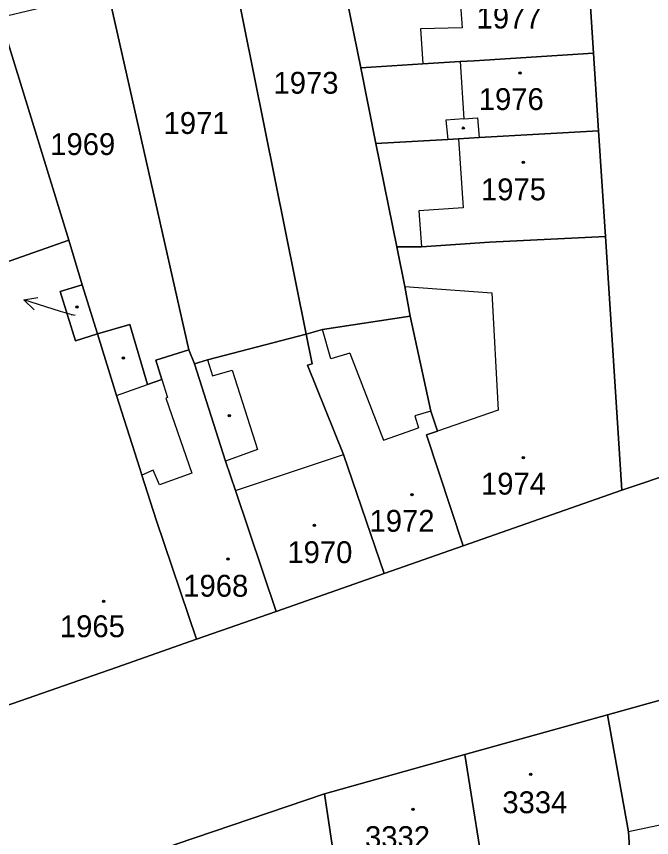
# Model space of a CAD drawing. Extents: x -596233 to -595156, y -1161235 to -1159375.
# Drawn here: x -595667.2 to -595617.7, y -1161083.2 to -1161019.3 of the extents above; entities that cross this region are included whole.
import ezdxf

# ---------------------------------------------------------------- set-up
doc = ezdxf.new("R2010")
doc.units = 0
for name, color, linetype in [('KN_CAR_KR', 7, 'Continuous'), ('KN_KULTURY', 7, 'Continuous'), ('KN_PARC_CIS_POM', 7, 'Continuous'), ('KN_PARC_CIS_POZ', 7, 'Continuous'), ('KN_PARC_CIS_STAV', 7, 'Continuous'), ('KN_PARC_PLOCHA', 7, 'Continuous'), ('PARC_C_SIPKA', 7, 'Continuous'), ('parcely_l', 7, 'Continuous')]:
    doc.layers.add(name, color=color, linetype=linetype)

msp = doc.modelspace()

# ---------------------------------------------------------------- linework, layer by layer
at = {"layer": 'KN_CAR_KR'}
for points in [[(-595632.78, -1161016), (-595632.49, -1161020.24)], [(-595632.49, -1161020.24), (-595635.72, -1161020.3)], [(-595635.72, -1161020.3), (-595635.55, -1161023.04)], [(-595632.63, -1161022.85), (-595632.35, -1161027.31)], [(-595632.35, -1161027.31), (-595633.74, -1161027.41)], [(-595632.35, -1161027.31), (-595631.28, -1161027.23)], [(-595631.28, -1161027.23), (-595631.15, -1161028.76)], [(-595633.74, -1161027.41), (-595633.6, -1161028.9)], [(-595632.76, -1161028.86), (-595632.4, -1161034.22)], [(-595632.4, -1161034.22), (-595635.84, -1161034.46)], [(-595635.84, -1161034.46), (-595635.65, -1161037.25)], [(-595636.93, -1161040.34), (-595630.16, -1161040.83)], [(-595630.16, -1161040.83), (-595629.68, -1161049.97)], [(-595642.7, -1161045.96), (-595643.34, -1161043.68)], [(-595641.22, -1161045.54), (-595642.7, -1161045.96)], [(-595641.22, -1161045.54), (-595638.59, -1161052.3)], [(-595652.28, -1161046.05), (-595651.91, -1161047.29)], [(-595651.91, -1161047.29), (-595650.38, -1161046.84)], [(-595650.38, -1161046.84), (-595648.39, -1161053.02)], [(-595655.84, -1161047.59), (-595655.41, -1161048.98)], [(-595659.38, -1161048.81), (-595656.97, -1161047.98)], [(-595655.41, -1161048.98), (-595655.54, -1161049.02)], [(-595655.54, -1161049.02), (-595653.51, -1161054.86)], [(-595634.91, -1161050.04), (-595636.15, -1161050.4)], [(-595629.68, -1161049.97), (-595634.4, -1161051.59)], [(-595636.15, -1161050.4), (-595635.87, -1161051.34)], [(-595638.59, -1161052.3), (-595635.87, -1161051.34)], [(-595648.39, -1161053.02), (-595650.88, -1161053.92)], [(-595650.11, -1161056.21), (-595641.72, -1161053.4)], [(-595656.53, -1161054.63), (-595657.39, -1161055.02)], [(-595656.02, -1161055.76), (-595656.53, -1161054.63)], [(-595653.51, -1161054.86), (-595656.02, -1161055.76)], [(-595615.99, -1161082), (-595619.53, -1161082.77)]]:
    msp.add_lwpolyline(points, dxfattribs=at)
at = {"layer": 'KN_KULTURY'}
for centre, radius in [((-595627.99, -1161023.75), 0.09), ((-595627.99, -1161023.75), 0.0398), ((-595632.4, -1161028.03), 0.09), ((-595632.4, -1161028.03), 0.0398), ((-595627.73, -1161030.69), 0.09), ((-595627.73, -1161030.69), 0.0398), ((-595662.45, -1161041.95), 0.09), ((-595662.45, -1161041.95), 0.0398), ((-595658.83, -1161045.91), 0.09), ((-595658.83, -1161045.91), 0.0398), ((-595650.6, -1161050.4), 0.09), ((-595650.6, -1161050.4), 0.0398), ((-595627.73, -1161053.65), 0.09), ((-595627.73, -1161053.65), 0.0398), ((-595636.38, -1161056.53), 0.09), ((-595636.38, -1161056.53), 0.0398), ((-595643.97, -1161058.93), 0.09), ((-595643.97, -1161058.93), 0.0398), ((-595650.7, -1161061.53), 0.09), ((-595650.7, -1161061.53), 0.0398), ((-595660.37, -1161064.84), 0.09), ((-595660.37, -1161064.84), 0.0398), ((-595627.14, -1161078.28), 0.09), ((-595627.14, -1161078.28), 0.0398), ((-595636.31, -1161081.01), 0.09), ((-595636.31, -1161081.01), 0.0398)]:
    msp.add_circle(centre, radius, dxfattribs=at)
at = {"layer": 'KN_PARC_PLOCHA'}
for points in [[(-595642.85, -1161010.99), (-595641.73, -1161016.57), (-595640.37, -1161023.34), (-595639.19, -1161029.22), (-595637.57, -1161037.26), (-595636.93, -1161040.34), (-595636.52, -1161042.66), (-595643.34, -1161043.68), (-595644.61, -1161044.04), (-595651.1, -1161011.83), (-595643.22, -1161009.14)], [(-595644.61, -1161044.04), (-595652.28, -1161046.05), (-595653.29, -1161046.35), (-595653.75, -1161045.27), (-595660.01, -1161017.46), (-595652.54, -1161012.74), (-595651.1, -1161011.83)], [(-595622.26, -1161022.21), (-595631.54, -1161022.79), (-595632.63, -1161022.85), (-595635.55, -1161023.04), (-595640.37, -1161023.34), (-595641.73, -1161016.57), (-595637.17, -1161016.28), (-595635.09, -1161016.14), (-595632.78, -1161016), (-595632.06, -1161015.95), (-595622.71, -1161015.36)], [(-595653.75, -1161045.27), (-595656.32, -1161046.07), (-595655.84, -1161047.59), (-595656.97, -1161047.98), (-595658.34, -1161043.3), (-595660.85, -1161044.03), (-595662.03, -1161040.21), (-595663.09, -1161036.75), (-595668.42, -1161019.4), (-595667.82, -1161019.28), (-595661.7, -1161017.8), (-595660.01, -1161017.46)], [(-595663.09, -1161036.75), (-595679.52, -1161042.53), (-595684.35, -1161029.96), (-595684.76, -1161028.79), (-595686.21, -1161024.68), (-595685.24, -1161024.28), (-595679.66, -1161022.52), (-595676.85, -1161021.56), (-595675.3, -1161021.09), (-595668.42, -1161019.4)], [(-595621.87, -1161028.23), (-595631.15, -1161028.76), (-595632.76, -1161028.86), (-595633.6, -1161028.9), (-595639.19, -1161029.22), (-595640.37, -1161023.34), (-595635.55, -1161023.04), (-595632.63, -1161022.85), (-595631.54, -1161022.79), (-595622.26, -1161022.21)], [(-595621.33, -1161036.46), (-595630.36, -1161036.9), (-595635.65, -1161037.25), (-595637.57, -1161037.26), (-595639.19, -1161029.22), (-595633.6, -1161028.9), (-595632.76, -1161028.86), (-595631.15, -1161028.76), (-595621.87, -1161028.23)], [(-595662.03, -1161040.21), (-595663.75, -1161040.74), (-595662.57, -1161044.56), (-595660.85, -1161044.03), (-595659.38, -1161048.81), (-595657.56, -1161054.5), (-595657.39, -1161055.02), (-595656.28, -1161058.5), (-595653.15, -1161067.78), (-595659.4, -1161069.97), (-595668.03, -1161072.98), (-595671.17, -1161064.61), (-595671.4, -1161064), (-595673.91, -1161057.31), (-595675.45, -1161053.19), (-595676.47, -1161050.46), (-595679.52, -1161042.53), (-595663.09, -1161036.75)], [(-595620.07, -1161056.19), (-595632.4, -1161060.51), (-595635.26, -1161051.88), (-595634.4, -1161051.59), (-595634.91, -1161050.04), (-595636.52, -1161042.66), (-595636.93, -1161040.34), (-595637.57, -1161037.26), (-595635.65, -1161037.25), (-595630.36, -1161036.9), (-595621.33, -1161036.46)], [(-595660.85, -1161044.03), (-595662.57, -1161044.56), (-595663.75, -1161040.74), (-595662.03, -1161040.21)], [(-595632.4, -1161060.51), (-595638.56, -1161062.67), (-595641.72, -1161053.4), (-595644.5, -1161046.46), (-595644.14, -1161046.36), (-595644.61, -1161044.04), (-595643.34, -1161043.68), (-595636.52, -1161042.66), (-595634.91, -1161050.04), (-595634.4, -1161051.59), (-595635.26, -1161051.88)], [(-595653.75, -1161045.27), (-595653.29, -1161046.35), (-595650.88, -1161053.92), (-595650.11, -1161056.21), (-595646.96, -1161065.61), (-595653.15, -1161067.78), (-595656.28, -1161058.5), (-595657.39, -1161055.02), (-595657.56, -1161054.5), (-595659.38, -1161048.81), (-595660.85, -1161044.03), (-595658.34, -1161043.3), (-595656.97, -1161047.98), (-595655.84, -1161047.59), (-595656.32, -1161046.07)], [(-595638.56, -1161062.67), (-595646.96, -1161065.61), (-595650.11, -1161056.21), (-595650.88, -1161053.92), (-595653.29, -1161046.35), (-595652.28, -1161046.05), (-595644.61, -1161044.04), (-595644.14, -1161046.36), (-595644.5, -1161046.46), (-595641.72, -1161053.4)], [(-595607.09, -1161088.75), (-595609.57, -1161089.08), (-595613.96, -1161089.04), (-595612.93, -1161095.54), (-595614.07, -1161095.65), (-595613.85, -1161097.15), (-595611.29, -1161096.84), (-595610.21, -1161105.21), (-595615.88, -1161105.95), (-595616.55, -1161101.2), (-595616.89, -1161101.2), (-595617.01, -1161101.2), (-595618.37, -1161092.42), (-595618.17, -1161092.39), (-595618.81, -1161088.35), (-595619.43, -1161084.4), (-595619.53, -1161082.77), (-595621.16, -1161073.65), (-595610.09, -1161070.58), (-595607.88, -1161079.68), (-595607.57, -1161083.19), (-595607.4, -1161085.24)], [(-595618.81, -1161088.35), (-595623.67, -1161088.91), (-595621.72, -1161107.66), (-595627.25, -1161108.52), (-595628, -1161103.71), (-595628.6, -1161099.94), (-595630.54, -1161087.63), (-595632.26, -1161076.75), (-595621.16, -1161073.65), (-595619.53, -1161082.77), (-595619.43, -1161084.4)], [(-595627.25, -1161108.52), (-595631.54, -1161109.12), (-595632.8, -1161109.28), (-595632.28, -1161113.48), (-595637.94, -1161114.26), (-595638.17, -1161112.67), (-595638.53, -1161110.1), (-595638.63, -1161109.2), (-595640.62, -1161096.67), (-595641.33, -1161091.91), (-595641.61, -1161090.39), (-595643.19, -1161079.8), (-595632.26, -1161076.75), (-595630.54, -1161087.63), (-595628.6, -1161099.94), (-595628, -1161103.71)], [(-595638.17, -1161112.67), (-595643.45, -1161113.53), (-595649.52, -1161114.51), (-595650.42, -1161109.18), (-595654.73, -1161083.72), (-595643.19, -1161079.8), (-595641.61, -1161090.39), (-595641.33, -1161091.91), (-595640.62, -1161096.67), (-595638.63, -1161109.2), (-595638.53, -1161110.1)]]:
    msp.add_lwpolyline(points, close=True, dxfattribs=at)
for points in [[(-595606.83, -1161051.74), (-595620.07, -1161056.19), (-595621.33, -1161036.46), (-595621.87, -1161028.23), (-595622.26, -1161022.21), (-595622.71, -1161015.36)], [(-595735.63, -1161096.54), (-595722.22, -1161091.87), (-595715.29, -1161089.45), (-595708.59, -1161087.12), (-595695.01, -1161082.38), (-595688.66, -1161080.17), (-595681.37, -1161077.63), (-595674.79, -1161075.34), (-595674.36, -1161075.19), (-595673.59, -1161074.92), (-595668.03, -1161072.98), (-595659.4, -1161069.97), (-595653.15, -1161067.78), (-595646.96, -1161065.61), (-595638.56, -1161062.67), (-595632.4, -1161060.51), (-595620.07, -1161056.19), (-595606.83, -1161051.74)], [(-595610.09, -1161070.58), (-595621.16, -1161073.65), (-595632.26, -1161076.75), (-595643.19, -1161079.8), (-595654.73, -1161083.72), (-595665.41, -1161087.54), (-595676.29, -1161091.44), (-595688.25, -1161095.72), (-595700.38, -1161100.11), (-595712.11, -1161104.36), (-595718, -1161106.49), (-595723.82, -1161108.53), (-595729.91, -1161110.67), (-595735.77, -1161112.73)]]:
    msp.add_lwpolyline(points, dxfattribs=at)
at = {"layer": 'PARC_C_SIPKA'}
for points in [[(-595665.7784, -1161042.166), (-595666.5858, -1161041.3926), (-595665.4826, -1161041.2108)], [(-595662.65, -1161042.61), (-595663.72, -1161042.28), (-595666.5858, -1161041.3926)]]:
    msp.add_lwpolyline(points, dxfattribs=at)
at = {"layer": 'parcely_l'}
for points in [[(-595644.61, -1161044.04), (-595651.1, -1161011.83)], [(-595622.71, -1161015.36), (-595622.26, -1161022.21)], [(-595641.73, -1161016.57), (-595640.37, -1161023.34)], [(-595653.75, -1161045.27), (-595660.01, -1161017.46)], [(-595668.42, -1161019.4), (-595663.09, -1161036.75)], [(-595622.26, -1161022.21), (-595631.54, -1161022.79), (-595632.63, -1161022.85), (-595635.55, -1161023.04), (-595640.37, -1161023.34)], [(-595622.26, -1161022.21), (-595621.87, -1161028.23)], [(-595640.37, -1161023.34), (-595639.19, -1161029.22)], [(-595639.19, -1161029.22), (-595633.6, -1161028.9), (-595632.76, -1161028.86), (-595631.15, -1161028.76), (-595621.87, -1161028.23)], [(-595621.87, -1161028.23), (-595621.33, -1161036.46)], [(-595639.19, -1161029.22), (-595637.57, -1161037.26)], [(-595663.09, -1161036.75), (-595679.52, -1161042.53)], [(-595662.03, -1161040.21), (-595663.09, -1161036.75)], [(-595637.57, -1161037.26), (-595635.65, -1161037.25), (-595630.36, -1161036.9), (-595621.33, -1161036.46)], [(-595621.33, -1161036.46), (-595620.07, -1161056.19)], [(-595636.52, -1161042.66), (-595636.93, -1161040.34), (-595637.57, -1161037.26)], [(-595660.85, -1161044.03), (-595662.57, -1161044.56), (-595663.75, -1161040.74), (-595662.03, -1161040.21)], [(-595662.03, -1161040.21), (-595660.85, -1161044.03)], [(-595644.61, -1161044.04), (-595643.34, -1161043.68), (-595636.52, -1161042.66)], [(-595636.52, -1161042.66), (-595634.91, -1161050.04), (-595634.4, -1161051.59), (-595635.26, -1161051.88), (-595632.4, -1161060.51)], [(-595660.85, -1161044.03), (-595658.34, -1161043.3), (-595656.97, -1161047.98), (-595655.84, -1161047.59), (-595656.32, -1161046.07), (-595653.75, -1161045.27)], [(-595653.15, -1161067.78), (-595656.28, -1161058.5), (-595657.39, -1161055.02), (-595657.56, -1161054.5), (-595659.38, -1161048.81), (-595660.85, -1161044.03)], [(-595644.61, -1161044.04), (-595652.28, -1161046.05), (-595653.29, -1161046.35)], [(-595638.56, -1161062.67), (-595641.72, -1161053.4), (-595644.5, -1161046.46), (-595644.14, -1161046.36), (-595644.61, -1161044.04)], [(-595653.29, -1161046.35), (-595653.75, -1161045.27)], [(-595646.96, -1161065.61), (-595650.11, -1161056.21), (-595650.88, -1161053.92), (-595653.29, -1161046.35)], [(-595620.07, -1161056.19), (-595606.83, -1161051.74)], [(-595620.07, -1161056.19), (-595632.4, -1161060.51)], [(-595632.4, -1161060.51), (-595638.56, -1161062.67)], [(-595646.96, -1161065.61), (-595638.56, -1161062.67)], [(-595653.15, -1161067.78), (-595646.96, -1161065.61)], [(-595668.03, -1161072.98), (-595659.4, -1161069.97), (-595653.15, -1161067.78)], [(-595610.09, -1161070.58), (-595621.16, -1161073.65)], [(-595621.16, -1161073.65), (-595632.26, -1161076.75)], [(-595618.81, -1161088.35), (-595619.43, -1161084.4), (-595619.53, -1161082.77), (-595621.16, -1161073.65)], [(-595632.26, -1161076.75), (-595643.19, -1161079.8)], [(-595627.25, -1161108.52), (-595628, -1161103.71), (-595628.6, -1161099.94), (-595630.54, -1161087.63), (-595632.26, -1161076.75)], [(-595643.19, -1161079.8), (-595654.73, -1161083.72)], [(-595643.19, -1161079.8), (-595641.61, -1161090.39), (-595641.33, -1161091.91), (-595640.62, -1161096.67), (-595638.63, -1161109.2), (-595638.53, -1161110.1), (-595638.17, -1161112.67)]]:
    msp.add_lwpolyline(points, dxfattribs=at)

# ---------------------------------------------------------------- texts
at = {"layer": 'KN_PARC_CIS_POM'}
msp.add_text('1967/2', height=0.1, dxfattribs=at).set_placement((-595662.9333, -1161042.61))
at = {"layer": 'KN_PARC_CIS_POZ'}
for s, p in [('1973', (-595647.1566, -1161025.35)), ('1971', (-595655.7066, -1161028.48)), ('1969', (-595664.5266, -1161030.12))]:
    msp.add_text(s, height=1.7, dxfattribs=at).set_placement(p)
at = {"layer": 'KN_PARC_CIS_STAV'}
for s, p in [('1977', (-595631.3566, -1161020.28)), ('1976', (-595631.1866, -1161026.62)), ('1975', (-595631.0166, -1161033.64)), ('1974', (-595631.0166, -1161056.53)), ('1972', (-595639.6866, -1161059.42)), ('1970', (-595646.0766, -1161061.86)), ('1968', (-595654.1766, -1161064.47)), ('1965', (-595663.7766, -1161067.62)), ('3334', (-595629.3566, -1161081.31)), ('3332', (-595640.0366, -1161084.02))]:
    msp.add_text(s, height=1.7, dxfattribs=at).set_placement(p)

doc.saveas('drawing.dxf')
